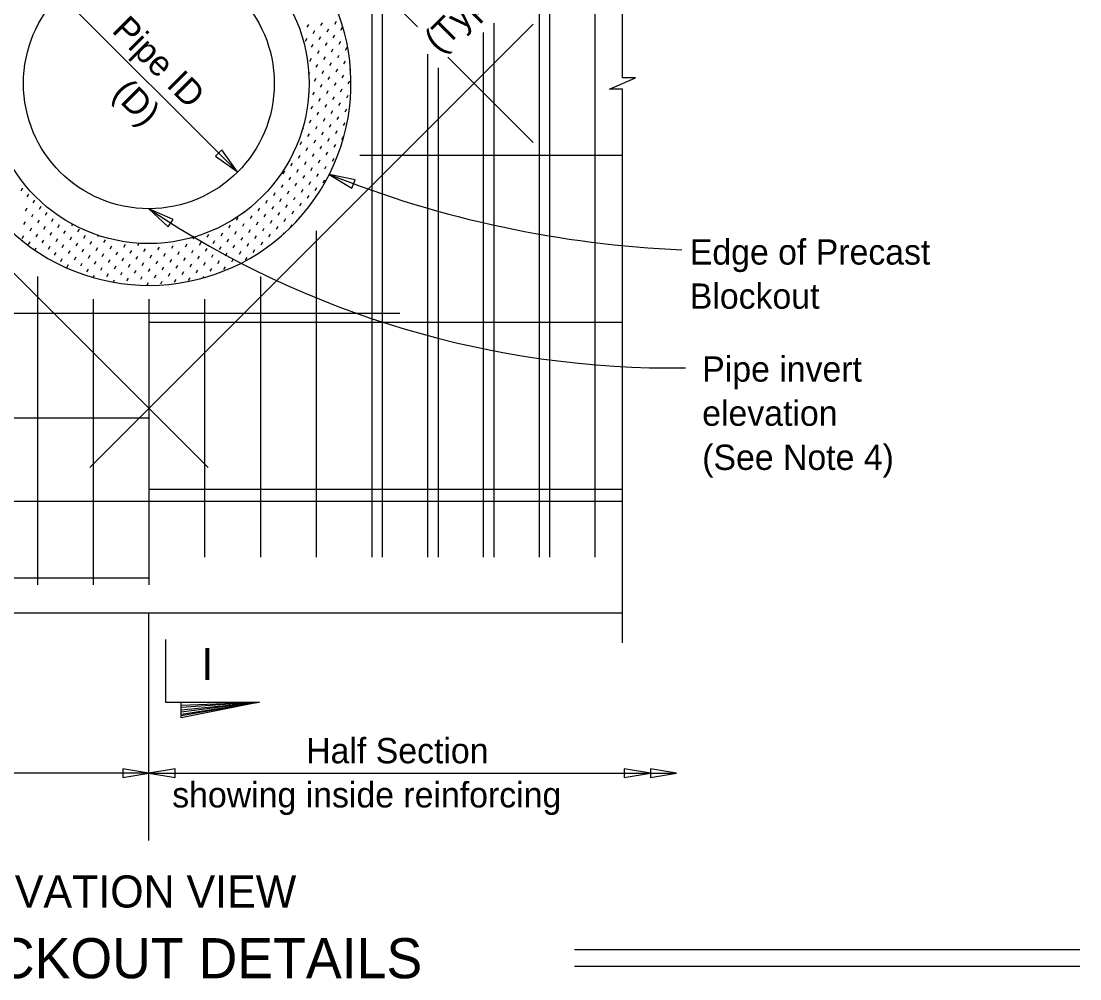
# Model space of a CAD drawing. Extents: x 10605.2 to 10672.7, y 76423.8 to 76450.2.
# Drawn here: x 10643.8 to 10650.13, y 76428.89 to 76434.62 of the extents above; entities that cross this region are included whole.
import ezdxf

# ---------------------------------------------------------------- set-up
doc = ezdxf.new("R2010")
doc.units = 0
for name, color, linetype in [('AdhocPoint_dp', 7, 'Continuous'), ('Border', 7, 'Continuous'), ('Patterning', 7, 'Continuous'), ('PlotBorder_dp', 7, 'Continuous'), ('SheetBorder_dp', 7, 'Continuous'), ('SheetLines_dp', 7, 'Continuous'), ('TextMisc', 7, 'Continuous')]:
    doc.layers.add(name, color=color, linetype=linetype)

msp = doc.modelspace()

# ---------------------------------------------------------------- linework, layer by layer
at = {"layer": 'AdhocPoint_dp'}
for p, q in [((10645.0945, 76433.7181), (10644.0369, 76434.7757)), ((10644.7597, 76430.5263), (10645.2285, 76430.5438)), ((10645.2285, 76430.5438), (10644.7597, 76430.5113)), ((10644.7597, 76430.4975), (10645.2285, 76430.5438)), ((10645.2285, 76430.5438), (10644.7597, 76430.4838)), ((10644.7597, 76430.4713), (10645.2285, 76430.5438)), ((10645.2285, 76430.5438), (10644.7597, 76430.4613)), ((10644.5672, 76430.1189), (10641.3251, 76430.1189)), ((10644.5672, 76430.1189), (10647.7222, 76430.1189)), ((10650.1345, 76429.0624), (10647.1123, 76429.0624)), ((10650.1345, 76428.962), (10647.1123, 76428.962))]:
    msp.add_line(p, q, dxfattribs=at)
for points in [[(10647.4003, 76430.898), (10647.4003, 76434.2116), (10647.3228, 76434.2116), (10647.4003, 76434.2454), (10647.4778, 76434.2791), (10647.4003, 76434.2791), (10647.4003, 76437.5929)], [(10644.666, 76430.9188), (10644.666, 76430.5438), (10645.2285, 76430.5438), (10644.7597, 76430.45), (10644.7597, 76430.5438)]]:
    msp.add_lwpolyline(points, dxfattribs=at)
for points in [[(10645.0945, 76433.7181), (10645.0028, 76433.8473), (10644.9654, 76433.8099)], [(10645.6458, 76433.7006), (10645.7811, 76433.6183), (10645.8007, 76433.6675)], [(10644.5672, 76433.4954), (10644.6823, 76433.3865), (10644.7117, 76433.4305)], [(10644.5672, 76430.1189), (10644.411, 76430.1454), (10644.411, 76430.0924)], [(10644.5672, 76430.1189), (10644.7234, 76430.0924), (10644.7234, 76430.1454)], [(10647.566, 76430.1189), (10647.4098, 76430.1454), (10647.4098, 76430.0925)], [(10647.7222, 76430.1189), (10647.566, 76430.1454), (10647.566, 76430.0925)]]:
    msp.add_lwpolyline(points, close=True, dxfattribs=at)
for centre, radius, start, end in [((10648.031, 76439.703), 6.459, 248.32774, 267.54428), ((10647.7001, 76438.1728), 5.6297, 236.18593, 270.76865)]:
    msp.add_arc(centre, radius, start, end, dxfattribs=at)
at = {"layer": 'Border'}
for p, q in [((10644.5672, 76432.9538), (10644.5672, 76432.551)), ((10644.5672, 76429.7159), (10644.5672, 76431.0788))]:
    msp.add_line(p, q, dxfattribs=at)
at = {"layer": 'Patterning'}
for p, q in [((10645.9004, 76437.0787), (10645.9004, 76431.4121)), ((10645.9629, 76437.0787), (10645.9629, 76431.4121)), ((10646.9003, 76437.0787), (10646.9003, 76431.4121)), ((10646.9628, 76437.0787), (10646.9628, 76431.4121)), ((10647.2336, 76437.0787), (10647.2336, 76431.4121)), ((10644.2137, 76436.5435), (10646.1735, 76434.5837)), ((10644.9208, 76431.9473), (10642.2691, 76434.5989)), ((10644.2137, 76431.9473), (10646.8653, 76434.5989)), ((10646.6295, 76434.6049), (10646.6295, 76431.4121)), ((10646.567, 76434.5503), (10646.567, 76431.4121)), ((10646.2337, 76434.421), (10646.2337, 76431.4121)), ((10646.3556, 76434.4015), (10646.8653, 76433.8918)), ((10646.2962, 76434.3392), (10646.2962, 76431.4121)), ((10645.8297, 76433.817), (10647.4003, 76433.817)), ((10645.5671, 76433.3636), (10645.5671, 76431.4121)), ((10643.9006, 76433.0908), (10643.9006, 76431.2455)), ((10645.2338, 76433.0908), (10645.2338, 76431.4121)), ((10644.2339, 76432.9545), (10644.2339, 76431.2455)), ((10644.9005, 76432.9545), (10644.9005, 76431.4121)), ((10644.5672, 76432.9122), (10644.5672, 76431.2455)), ((10643.0672, 76432.8704), (10646.0672, 76432.8704)), ((10644.5672, 76432.817), (10647.4003, 76432.817)), ((10641.7341, 76432.2455), (10644.5672, 76432.2455)), ((10644.5672, 76431.8172), (10647.4003, 76431.8172)), ((10641.7341, 76431.2872), (10644.5672, 76431.2872))]:
    msp.add_line(p, q, dxfattribs=at)
at = {"layer": 'PlotBorder_dp'}
msp.add_line((10641.7341, 76431.0788), (10647.4003, 76431.0788), dxfattribs=at)
msp.add_circle((10644.5672, 76434.2454), 0.75, dxfattribs=at)
msp.add_arc((10644.5672, 76434.2454), 1.2083, 58.21293, 50.39786, dxfattribs=at)
at = {"layer": 'SheetLines_dp'}
for p, q in [((10645.5133, 76434.5812), (10645.523, 76434.598)), ((10645.5962, 76434.5909), (10645.606, 76434.6077)), ((10645.6792, 76434.6006), (10645.6889, 76434.6174)), ((10645.4755, 76434.5497), (10645.4766, 76434.5516)), ((10645.5499, 76434.5446), (10645.5596, 76434.5613)), ((10645.5865, 76434.5079), (10645.5962, 76434.5247)), ((10645.6329, 76434.5543), (10645.6426, 76434.5711)), ((10645.6695, 76434.5176), (10645.6792, 76434.5344)), ((10645.7158, 76434.564), (10645.7256, 76434.5808)), ((10645.5035, 76434.4982), (10645.5133, 76434.515)), ((10645.5402, 76434.4616), (10645.5499, 76434.4784)), ((10645.6231, 76434.4713), (10645.6329, 76434.4881)), ((10645.7061, 76434.481), (10645.7158, 76434.4978)), ((10645.7427, 76434.4444), (10645.7525, 76434.4612)), ((10645.5304, 76434.3786), (10645.5402, 76434.3954)), ((10645.5768, 76434.4249), (10645.5865, 76434.4417)), ((10645.6134, 76434.3883), (10645.6231, 76434.4051)), ((10645.6598, 76434.4347), (10645.6695, 76434.4515)), ((10645.6964, 76434.398), (10645.7061, 76434.4148)), ((10645.5671, 76434.342), (10645.5768, 76434.3588)), ((10645.65, 76434.3517), (10645.6598, 76434.3685)), ((10645.6867, 76434.3151), (10645.6964, 76434.3319)), ((10645.733, 76434.3614), (10645.7427, 76434.3782)), ((10645.7697, 76434.3248), (10645.7726, 76434.3298)), ((10645.5227, 76434.2991), (10645.5304, 76434.3124)), ((10645.5573, 76434.259), (10645.5671, 76434.2758)), ((10645.6037, 76434.3053), (10645.6134, 76434.3221)), ((10645.6403, 76434.2687), (10645.65, 76434.2855)), ((10645.7233, 76434.2784), (10645.733, 76434.2952)), ((10645.594, 76434.2224), (10645.6037, 76434.2392)), ((10645.6306, 76434.1857), (10645.6403, 76434.2025)), ((10645.677, 76434.2321), (10645.6867, 76434.2489)), ((10645.7136, 76434.1955), (10645.7233, 76434.2122)), ((10645.7599, 76434.2418), (10645.7697, 76434.2586)), ((10645.5476, 76434.176), (10645.5573, 76434.1928)), ((10645.5842, 76434.1394), (10645.594, 76434.1562)), ((10645.6672, 76434.1491), (10645.677, 76434.1659)), ((10645.7502, 76434.1588), (10645.7599, 76434.1756)), ((10645.5379, 76434.093), (10645.5476, 76434.1098)), ((10645.6209, 76434.1028), (10645.6306, 76434.1195)), ((10645.6575, 76434.0661), (10645.6672, 76434.0829)), ((10645.7039, 76434.1125), (10645.7136, 76434.1293)), ((10645.7405, 76434.0758), (10645.7502, 76434.0926)), ((10645.5282, 76434.01), (10645.5379, 76434.0268)), ((10645.5745, 76434.0564), (10645.5842, 76434.0732)), ((10645.6112, 76434.0198), (10645.6209, 76434.0366)), ((10645.6941, 76434.0295), (10645.7039, 76434.0463)), ((10645.4831, 76433.9658), (10645.4915, 76433.9805)), ((10645.5648, 76433.9734), (10645.5745, 76433.9902)), ((10645.6014, 76433.9368), (10645.6112, 76433.9536)), ((10645.6478, 76433.9831), (10645.6575, 76433.9999)), ((10645.6844, 76433.9465), (10645.6941, 76433.9633)), ((10645.7308, 76433.9929), (10645.7405, 76434.0097)), ((10645.4721, 76433.8807), (10645.4818, 76433.8975)), ((10645.5185, 76433.9271), (10645.5282, 76433.9439)), ((10645.5551, 76433.8904), (10645.5648, 76433.9072)), ((10645.6381, 76433.9002), (10645.6478, 76433.917)), ((10645.721, 76433.9099), (10645.7308, 76433.9267)), ((10645.5087, 76433.8441), (10645.5185, 76433.8609)), ((10645.5454, 76433.8075), (10645.5551, 76433.8243)), ((10645.5917, 76433.8538), (10645.6014, 76433.8706)), ((10645.6283, 76433.8172), (10645.6381, 76433.834)), ((10645.6747, 76433.8635), (10645.6844, 76433.8803)), ((10645.416, 76433.7514), (10645.4258, 76433.7682)), ((10645.4624, 76433.7977), (10645.4721, 76433.8145)), ((10645.499, 76433.7611), (10645.5087, 76433.7779)), ((10645.582, 76433.7708), (10645.5917, 76433.7876)), ((10645.665, 76433.7806), (10645.6747, 76433.7974)), ((10645.3697, 76433.705), (10645.3794, 76433.7218)), ((10645.4527, 76433.7148), (10645.4624, 76433.7316)), ((10645.4893, 76433.6781), (10645.499, 76433.6949)), ((10645.5356, 76433.7245), (10645.5454, 76433.7413)), ((10645.5723, 76433.6879), (10645.582, 76433.7047)), ((10645.6186, 76433.7342), (10645.6283, 76433.751)), ((10645.36, 76433.6221), (10645.3697, 76433.6389)), ((10645.4063, 76433.6684), (10645.416, 76433.6852)), ((10645.4429, 76433.6318), (10645.4527, 76433.6486)), ((10645.5259, 76433.6415), (10645.5356, 76433.6583)), ((10645.6089, 76433.6512), (10645.6186, 76433.668)), ((10643.8028, 76433.6033), (10643.8125, 76433.6201)), ((10643.8394, 76433.5667), (10643.8492, 76433.5835)), ((10645.3136, 76433.5757), (10645.3233, 76433.5925)), ((10645.3966, 76433.5854), (10645.4063, 76433.6022)), ((10645.4796, 76433.5952), (10645.4893, 76433.6119)), ((10645.5162, 76433.5585), (10645.5259, 76433.5753)), ((10645.5625, 76433.6049), (10645.5723, 76433.6217)), ((10643.8761, 76433.53), (10643.8858, 76433.5468)), ((10643.9127, 76433.4934), (10643.9224, 76433.5102)), ((10645.2673, 76433.5294), (10645.277, 76433.5462)), ((10645.3039, 76433.4927), (10645.3136, 76433.5095)), ((10645.3502, 76433.5391), (10645.36, 76433.5559)), ((10645.3869, 76433.5025), (10645.3966, 76433.5192)), ((10645.4332, 76433.5488), (10645.4429, 76433.5656)), ((10645.4698, 76433.5122), (10645.4796, 76433.529)), ((10643.8297, 76433.4837), (10643.8394, 76433.5005)), ((10643.8663, 76433.4471), (10643.8761, 76433.4638)), ((10643.9493, 76433.4568), (10643.959, 76433.4736)), ((10645.0916, 76433.4269), (10645.1013, 76433.4437)), ((10645.1379, 76433.4733), (10645.141, 76433.4786)), ((10645.1746, 76433.4367), (10645.1843, 76433.4535)), ((10645.2209, 76433.483), (10645.2306, 76433.4998)), ((10645.2575, 76433.4464), (10645.2673, 76433.4632)), ((10645.3405, 76433.4561), (10645.3502, 76433.4729)), ((10645.4235, 76433.4658), (10645.4332, 76433.4826)), ((10645.464, 76433.4358), (10645.4698, 76433.446)), ((10643.82, 76433.4007), (10643.8297, 76433.4175)), ((10643.8566, 76433.3641), (10643.8663, 76433.3809)), ((10643.903, 76433.4104), (10643.9127, 76433.4272)), ((10643.9396, 76433.3738), (10643.9493, 76433.3906)), ((10643.9859, 76433.4201), (10643.9957, 76433.4369)), ((10644.0226, 76433.3835), (10644.0323, 76433.4003)), ((10644.1055, 76433.3932), (10644.1115, 76433.4035)), ((10645.0452, 76433.3806), (10645.0549, 76433.3974)), ((10645.1282, 76433.3903), (10645.1379, 76433.4071)), ((10645.2112, 76433.4), (10645.2209, 76433.4168)), ((10645.2478, 76433.3634), (10645.2575, 76433.3802)), ((10645.2942, 76433.4098), (10645.3039, 76433.4265)), ((10645.3308, 76433.3731), (10645.3405, 76433.3899)), ((10645.3771, 76433.4195), (10645.3869, 76433.4363)), ((10645.4145, 76433.3841), (10645.4235, 76433.3996)), ((10643.8103, 76433.3177), (10643.82, 76433.3345)), ((10643.8932, 76433.3274), (10643.903, 76433.3442)), ((10643.9762, 76433.3372), (10643.9859, 76433.354)), ((10644.0128, 76433.3005), (10644.0226, 76433.3173)), ((10644.0592, 76433.3469), (10644.0689, 76433.3637)), ((10644.0958, 76433.3103), (10644.1055, 76433.3271)), ((10644.1422, 76433.3566), (10644.1519, 76433.3734)), ((10644.1788, 76433.32), (10644.1885, 76433.3368)), ((10644.2618, 76433.3297), (10644.2655, 76433.3361)), ((10644.8329, 76433.3148), (10644.8405, 76433.3279)), ((10644.9159, 76433.3245), (10644.9256, 76433.3413)), ((10644.9622, 76433.3709), (10644.9637, 76433.3734)), ((10644.9989, 76433.3342), (10645.0086, 76433.351)), ((10645.0819, 76433.344), (10645.0916, 76433.3607)), ((10645.1185, 76433.3073), (10645.1282, 76433.3241)), ((10645.1648, 76433.3537), (10645.1746, 76433.3705)), ((10645.2015, 76433.317), (10645.2112, 76433.3338)), ((10645.2844, 76433.3268), (10645.2942, 76433.3436)), ((10645.3719, 76433.3443), (10645.3771, 76433.3533)), ((10643.8469, 76433.2811), (10643.8566, 76433.2979)), ((10643.8855, 76433.2479), (10643.8932, 76433.2613)), ((10643.9299, 76433.2908), (10643.9396, 76433.3076)), ((10643.9665, 76433.2542), (10643.9762, 76433.271)), ((10644.0495, 76433.2639), (10644.0592, 76433.2807)), ((10644.1325, 76433.2736), (10644.1422, 76433.2904)), ((10644.1691, 76433.237), (10644.1788, 76433.2538)), ((10644.2154, 76433.2834), (10644.2252, 76433.3001)), ((10644.2521, 76433.2467), (10644.2618, 76433.2635)), ((10644.2984, 76433.2931), (10644.3081, 76433.3099)), ((10644.335, 76433.2565), (10644.3448, 76433.2732)), ((10644.3814, 76433.3028), (10644.383, 76433.3057)), ((10644.418, 76433.2662), (10644.4277, 76433.283)), ((10644.501, 76433.2759), (10644.5092, 76433.2901)), ((10644.5376, 76433.2393), (10644.5473, 76433.2561)), ((10644.584, 76433.2856), (10644.5854, 76433.288)), ((10644.6206, 76433.249), (10644.6303, 76433.2658)), ((10644.7036, 76433.2587), (10644.7133, 76433.2755)), ((10644.7499, 76433.3051), (10644.7502, 76433.3055)), ((10644.7866, 76433.2684), (10644.7963, 76433.2852)), ((10644.8695, 76433.2782), (10644.8793, 76433.295)), ((10644.9062, 76433.2415), (10644.9159, 76433.2583)), ((10644.9525, 76433.2879), (10644.9622, 76433.3047)), ((10644.9891, 76433.2513), (10644.9989, 76433.268)), ((10645.0355, 76433.2976), (10645.0452, 76433.3144)), ((10645.0721, 76433.261), (10645.0819, 76433.2778)), ((10645.1551, 76433.2707), (10645.1648, 76433.2875)), ((10645.2381, 76433.2804), (10645.2478, 76433.2972)), ((10643.9274, 76433.2204), (10643.9299, 76433.2246)), ((10644.0031, 76433.2176), (10644.0128, 76433.2344)), ((10644.0398, 76433.1809), (10644.0495, 76433.1977)), ((10644.0861, 76433.2273), (10644.0958, 76433.2441)), ((10644.1227, 76433.1907), (10644.1325, 76433.2074)), ((10644.2057, 76433.2004), (10644.2154, 76433.2172)), ((10644.2887, 76433.2101), (10644.2984, 76433.2269)), ((10644.3253, 76433.1735), (10644.335, 76433.1903)), ((10644.3717, 76433.2198), (10644.3814, 76433.2366)), ((10644.4083, 76433.1832), (10644.418, 76433.2)), ((10644.4546, 76433.2295), (10644.4644, 76433.2463)), ((10644.4913, 76433.1929), (10644.501, 76433.2097)), ((10644.5743, 76433.2026), (10644.584, 76433.2194)), ((10644.6572, 76433.2124), (10644.667, 76433.2292)), ((10644.6939, 76433.1757), (10644.7036, 76433.1925)), ((10644.7402, 76433.2221), (10644.7499, 76433.2389)), ((10644.7768, 76433.1855), (10644.7866, 76433.2023)), ((10644.8232, 76433.2318), (10644.8329, 76433.2486)), ((10644.8598, 76433.1952), (10644.8695, 76433.212)), ((10644.9428, 76433.2049), (10644.9525, 76433.2217)), ((10645.0258, 76433.2146), (10645.0355, 76433.2314)), ((10645.0624, 76433.178), (10645.0721, 76433.1948)), ((10645.1088, 76433.2243), (10645.1185, 76433.2411)), ((10645.1454, 76433.1877), (10645.1551, 76433.2045)), ((10645.1917, 76433.2341), (10645.2015, 76433.2509)), ((10644.0764, 76433.1443), (10644.0861, 76433.1611)), ((10644.1594, 76433.154), (10644.1691, 76433.1708)), ((10644.196, 76433.1174), (10644.2057, 76433.1342)), ((10644.2423, 76433.1637), (10644.2521, 76433.1805)), ((10644.279, 76433.1271), (10644.2887, 76433.1439)), ((10644.3619, 76433.1368), (10644.3717, 76433.1536)), ((10644.4449, 76433.1466), (10644.4546, 76433.1634)), ((10644.4816, 76433.1099), (10644.4913, 76433.1267)), ((10644.5279, 76433.1563), (10644.5376, 76433.1731)), ((10644.5645, 76433.1197), (10644.5743, 76433.1365)), ((10644.6109, 76433.166), (10644.6206, 76433.1828)), ((10644.6475, 76433.1294), (10644.6572, 76433.1462)), ((10644.7305, 76433.1391), (10644.7402, 76433.1559)), ((10644.8135, 76433.1488), (10644.8232, 76433.1656)), ((10644.8501, 76433.1122), (10644.8598, 76433.129)), ((10644.8964, 76433.1586), (10644.9062, 76433.1753)), ((10644.9331, 76433.1219), (10644.9428, 76433.1387)), ((10644.9794, 76433.1683), (10644.9891, 76433.1851)), ((10645.0161, 76433.1316), (10645.0258, 76433.1484)), ((10644.1215, 76433.1223), (10644.1227, 76433.1245)), ((10644.2344, 76433.0839), (10644.2423, 76433.0976)), ((10644.3156, 76433.0905), (10644.3253, 76433.1073)), ((10644.3536, 76433.0563), (10644.3619, 76433.0707)), ((10644.3986, 76433.1002), (10644.4083, 76433.117)), ((10644.4352, 76433.0636), (10644.4449, 76433.0804)), ((10644.5182, 76433.0733), (10644.5279, 76433.0901)), ((10644.6012, 76433.083), (10644.6109, 76433.0998)), ((10644.6378, 76433.0464), (10644.6475, 76433.0632)), ((10644.6841, 76433.0928), (10644.6939, 76433.1095)), ((10644.7208, 76433.0561), (10644.7305, 76433.0729)), ((10644.7671, 76433.1025), (10644.7768, 76433.1193)), ((10644.8037, 76433.0658), (10644.8135, 76433.0826)), ((10644.89, 76433.0812), (10644.8964, 76433.0924)), ((10644.4796, 76433.0404), (10644.4816, 76433.0438)), ((10644.5552, 76433.0373), (10644.5645, 76433.0535))]:
    msp.add_line(p, q, dxfattribs=at)
at = {"layer": 'TextMisc'}
msp.add_line((10641.7341, 76431.7454), (10647.4003, 76431.7454), dxfattribs=at)
msp.add_circle((10644.5672, 76434.2454), 0.9583, dxfattribs=at)

# ---------------------------------------------------------------- texts
at = {"layer": 'AdhocPoint_dp'}
for s, rotation, p in [('(Typ.)', 45, (10646.3056, 76434.4194)), ('Pipe ID', 315, (10644.34, 76434.5558)), ('(D)', 315, (10644.3429, 76434.1796))]:
    msp.add_text(s, height=0.1512, rotation=rotation, dxfattribs=at).set_placement(p)
for s, p in [('Edge of Precast', (10647.802, 76433.1614)), ('Blockout', (10647.802, 76432.8974)), ('Pipe invert', (10647.8762, 76432.4611)), ('elevation', (10647.8762, 76432.1971)), ('(See Note 4)', (10647.8762, 76431.9331)), ('Half Section', (10645.5081, 76430.1781)), ('showing inside reinforcing', (10644.7069, 76429.9141))]:
    msp.add_text(s, height=0.1512, dxfattribs=at).set_placement(p)
at = {"layer": 'SheetBorder_dp'}
for s, height, p in [('I', 0.192, (10644.882, 76430.6761)), ('ELEVATION VIEW', 0.192, (10643.2801, 76429.3155)), ('PIPE BLOCKOUT DETAILS', 0.24, (10642.1893, 76428.8922))]:
    msp.add_text(s, height=height, dxfattribs=at).set_placement(p)

doc.saveas('drawing.dxf')
